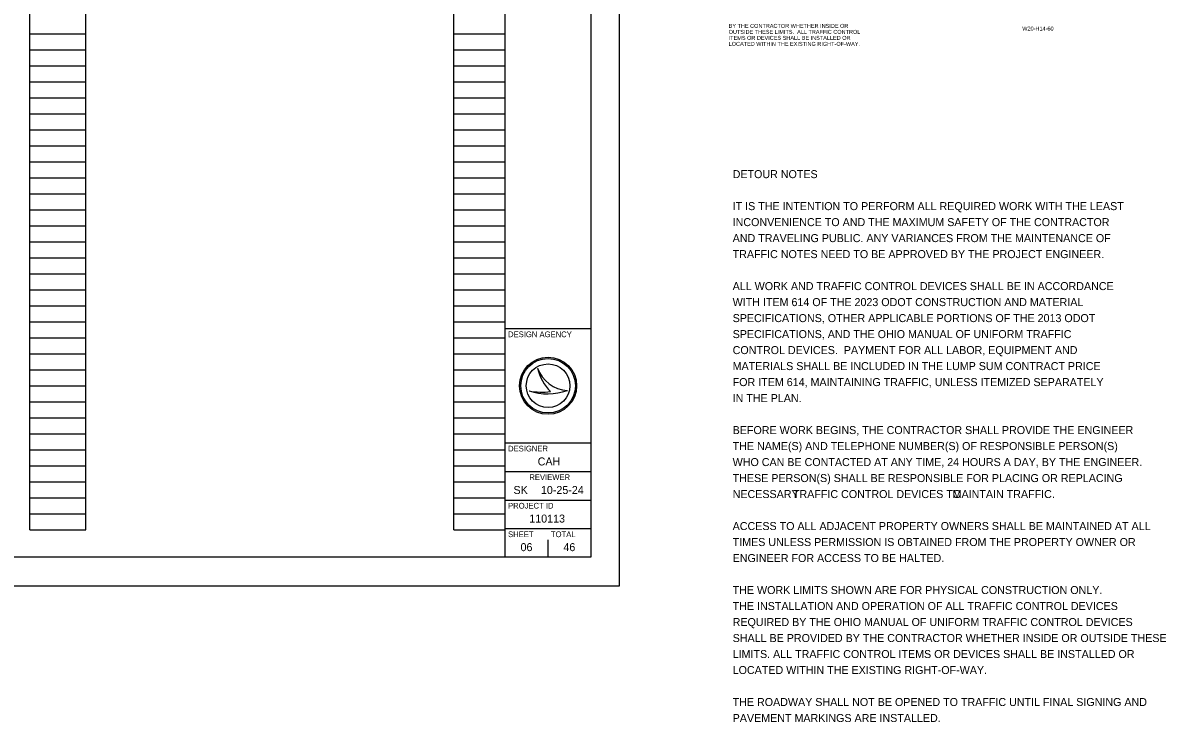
# Model space of a CAD drawing. Extents: x -98 to 46, y -2 to 66.
# Drawn here: x 23.56 to 43.57, y -2.39 to 9.85 of the extents above; entities that cross this region are included whole.
import ezdxf

# ---------------------------------------------------------------- set-up
doc = ezdxf.new("R2010")
doc.units = 0
for name, color, linetype in [('SC_Scratch1', 7, 'Continuous'), ('SH_Border', 7, 'Continuous'), ('SH_Cut_Line', 7, 'Continuous'), ('SH_Data', 7, 'Continuous'), ('SN_P_Text', 7, 'Continuous')]:
    doc.layers.add(name, color=color, linetype=linetype)

msp = doc.modelspace()

# ---------------------------------------------------------------- linework, layer by layer
at = {"layer": 'SH_Border'}
for p, q in [((32, 0.5), (32, 21.5)), ((32, 4.5), (33.5, 4.5)), ((32, 2.5), (33.5, 2.5)), ((32, 2), (33.5, 2)), ((32, 1.5), (33.5, 1.5)), ((32, 1), (33.5, 1))]:
    msp.add_line(p, q, dxfattribs=at)
msp.add_lwpolyline([(1.5, 21.5), (33.5, 21.5), (33.5, 0.5), (1.5, 0.5)], close=True, dxfattribs=at)
at = {"layer": 'SH_Cut_Line'}
msp.add_lwpolyline([(0, 0), (34, 0), (34, 22), (0, 22)], close=True, dxfattribs=at)
at = {"layer": 'SH_Data'}
for p, q in [((23.68, 0.98), (23.68, 21.14)), ((24.66, 0.98), (24.66, 21.14)), ((31.1, 0.98), (31.1, 21.14)), ((32, 0.98), (32, 21.14)), ((23.68, 9.66), (24.66, 9.66)), ((31.1, 9.66), (32, 9.66)), ((23.68, 9.38), (24.66, 9.38)), ((31.1, 9.38), (32, 9.38)), ((23.68, 9.1), (24.66, 9.1)), ((31.1, 9.1), (32, 9.1)), ((23.68, 8.82), (24.66, 8.82)), ((31.1, 8.82), (32, 8.82)), ((23.68, 8.54), (24.66, 8.54)), ((31.1, 8.54), (32, 8.54)), ((23.68, 8.26), (24.66, 8.26)), ((31.1, 8.26), (32, 8.26)), ((23.68, 7.98), (24.66, 7.98)), ((31.1, 7.98), (32, 7.98)), ((23.68, 7.7), (24.66, 7.7)), ((31.1, 7.7), (32, 7.7)), ((23.68, 7.42), (24.66, 7.42)), ((31.1, 7.42), (32, 7.42)), ((23.68, 7.14), (24.66, 7.14)), ((31.1, 7.14), (32, 7.14)), ((23.68, 6.86), (24.66, 6.86)), ((31.1, 6.86), (32, 6.86)), ((23.68, 6.58), (24.66, 6.58)), ((31.1, 6.58), (32, 6.58)), ((23.68, 6.3), (24.66, 6.3)), ((31.1, 6.3), (32, 6.3)), ((23.68, 6.02), (24.66, 6.02)), ((31.1, 6.02), (32, 6.02)), ((23.68, 5.74), (24.66, 5.74)), ((31.1, 5.74), (32, 5.74)), ((23.68, 5.46), (24.66, 5.46)), ((31.1, 5.46), (32, 5.46)), ((23.68, 5.18), (24.66, 5.18)), ((31.1, 5.18), (32, 5.18)), ((23.68, 4.9), (24.66, 4.9)), ((31.1, 4.9), (32, 4.9)), ((23.68, 4.62), (24.66, 4.62)), ((31.1, 4.62), (32, 4.62)), ((23.68, 4.34), (24.66, 4.34)), ((31.1, 4.34), (32, 4.34)), ((23.68, 4.06), (24.66, 4.06)), ((31.1, 4.06), (32, 4.06)), ((32.567, 3.81), (32.567, 3.81)), ((23.68, 3.78), (24.66, 3.78)), ((31.1, 3.78), (32, 3.78)), ((23.68, 3.5), (24.66, 3.5)), ((31.1, 3.5), (32, 3.5)), ((32.417, 3.41), (32.417, 3.41)), ((32.75, 3.5), (32.75, 3.5)), ((33.087, 3.419), (33.087, 3.419)), ((23.68, 3.22), (24.66, 3.22)), ((31.1, 3.22), (32, 3.22)), ((23.68, 2.94), (24.66, 2.94)), ((31.1, 2.94), (32, 2.94)), ((23.68, 2.66), (24.66, 2.66)), ((31.1, 2.66), (32, 2.66)), ((23.68, 2.38), (24.66, 2.38)), ((31.1, 2.38), (32, 2.38)), ((23.68, 2.1), (24.66, 2.1)), ((31.1, 2.1), (32, 2.1)), ((23.68, 1.82), (24.66, 1.82)), ((31.1, 1.82), (32, 1.82)), ((23.68, 1.54), (24.66, 1.54)), ((31.1, 1.54), (32, 1.54)), ((23.68, 1.26), (24.66, 1.26)), ((31.1, 1.26), (32, 1.26)), ((23.68, 0.98), (24.66, 0.98)), ((31.1, 0.98), (32, 0.98)), ((32.375, 0.675), (32.375, 0.675)), ((32.75, 0.5), (32.75, 0.8))]:
    msp.add_line(p, q, dxfattribs=at)
for radius in [0.5, 0.477, 0.477, 0.382]:
    msp.add_circle((32.75, 3.5), radius, dxfattribs=at)
for centre, radius, start, end in [((33.116, 3.998), 0.58, 198.9257, 198.9319), ((33.347, 3.97), 0.796, 191.6379, 191.6421), ((33.116, 3.998), 0.58, 198.9319, 267.1657), ((33.347, 3.97), 0.796, 191.6421, 226.0947), ((32.739, 4.37), 1.013, 251.4576, 290.0832), ((32.648, 4.654), 1.266, 259.4964, 259.4995), ((32.739, 4.37), 1.013, 251.4527, 251.4576), ((32.648, 4.654), 1.266, 259.4995, 276.6672)]:
    msp.add_arc(centre, radius, start, end, dxfattribs=at)

# ---------------------------------------------------------------- texts
at = {"layer": 'SC_Scratch1'}
for s, height, p in [('BY THE CONTRACTOR WHETHER INSIDE OR ', 0.07, (35.91, 9.764)), ('OUTSIDE THESE LIMITS.  ALL TRAFFIC CONTROL ', 0.07, (35.91, 9.659)), ('ITEMS OR DEVICES SHALL BE INSTALLED OR ', 0.07, (35.91, 9.554)), ('LOCATED WITHIN THE EXISTING RIGHT-OF-WAY.', 0.07, (35.91, 9.449)), ('DETOUR NOTES', 0.14, (35.98, 7.134)), ('IT IS THE INTENTION TO PERFORM ALL REQUIRED WORK WITH THE LEAST', 0.14, (35.98, 6.574)), ('INCONVENIENCE TO AND THE MAXIMUM SAFETY OF THE CONTRACTOR ', 0.14, (35.98, 6.294)), ('AND TRAVELING PUBLIC. ANY VARIANCES FROM THE MAINTENANCE OF ', 0.14, (35.98, 6.014)), ('TRAFFIC NOTES NEED TO BE APPROVED BY THE PROJECT ENGINEER.', 0.14, (35.98, 5.734)), ('ALL WORK AND TRAFFIC CONTROL DEVICES SHALL BE IN ACCORDANCE ', 0.14, (35.98, 5.174)), ('WITH ITEM 614 OF THE 2023 ODOT CONSTRUCTION AND MATERIAL ', 0.14, (35.98, 4.894)), ('SPECIFICATIONS, OTHER APPLICABLE PORTIONS OF THE 2013 ODOT ', 0.14, (35.98, 4.614)), ('SPECIFICATIONS, AND THE OHIO MANUAL OF UNIFORM TRAFFIC ', 0.14, (35.98, 4.334)), ('CONTROL DEVICES.  PAYMENT FOR ALL LABOR, EQUIPMENT AND ', 0.14, (35.98, 4.054)), ('MATERIALS SHALL BE INCLUDED IN THE LUMP SUM CONTRACT PRICE ', 0.14, (35.98, 3.774)), ('FOR ITEM 614, MAINTAINING TRAFFIC, UNLESS ITEMIZED SEPARATELY ', 0.14, (35.98, 3.494)), ('IN THE PLAN.', 0.14, (35.98, 3.214)), ('BEFORE WORK BEGINS, THE CONTRACTOR SHALL PROVIDE THE ENGINEER ', 0.14, (35.98, 2.654)), ('THE NAME(S) AND TELEPHONE NUMBER(S) OF RESPONSIBLE PERSON(S) ', 0.14, (35.98, 2.374)), ('WHO CAN BE CONTACTED AT ANY TIME, 24 HOURS A DAY, BY THE ENGINEER.  ', 0.14, (35.98, 2.094)), ('THESE PERSON(S) SHALL BE RESPONSIBLE FOR PLACING OR REPLACING ', 0.14, (35.98, 1.814)), ('NECESSARY ', 0.14, (35.98, 1.534)), ('TRAFFIC CONTROL DEVICES TO ', 0.14, (37.035, 1.534)), ('MAINTAIN TRAFFIC.', 0.14, (39.829, 1.534)), ('ACCESS TO ALL ADJACENT PROPERTY OWNERS SHALL BE MAINTAINED AT ALL ', 0.14, (35.98, 0.974)), ('TIMES UNLESS PERMISSION IS OBTAINED FROM THE PROPERTY OWNER OR', 0.14, (35.98, 0.694)), ('ENGINEER FOR ACCESS TO BE HALTED.', 0.14, (35.98, 0.414)), ('THE WORK LIMITS SHOWN ARE FOR PHYSICAL CONSTRUCTION ONLY.  ', 0.14, (35.98, -0.146)), ('THE INSTALLATION AND OPERATION OF ALL TRAFFIC CONTROL DEVICES ', 0.14, (35.98, -0.426)), ('REQUIRED BY THE OHIO MANUAL OF UNIFORM TRAFFIC CONTROL DEVICES', 0.14, (35.98, -0.706)), ('SHALL BE PROVIDED BY THE CONTRACTOR WHETHER INSIDE OR OUTSIDE THESE ', 0.14, (35.98, -0.986)), ('LIMITS. ALL TRAFFIC CONTROL ITEMS OR DEVICES SHALL BE INSTALLED OR ', 0.14, (35.98, -1.266)), ('LOCATED WITHIN THE EXISTING RIGHT-OF-WAY.', 0.14, (35.98, -1.546)), ('THE ROADWAY SHALL NOT BE OPENED TO TRAFFIC UNTIL FINAL SIGNING AND ', 0.14, (35.98, -2.106)), ('PAVEMENT MARKINGS ARE INSTALLED.', 0.14, (35.98, -2.386))]:
    msp.add_text(s, height=height, dxfattribs=at).set_placement(p)
at = {"layer": 'SH_Data'}
for s, height, p in [('DESIGN AGENCY', 0.1, (32.05, 4.35)), ('DESIGNER', 0.1, (32.05, 2.35)), ('CAH', 0.14, (32.568, 2.105)), ('REVIEWER', 0.1, (32.422, 1.85)), ('SK', 0.14, (32.145, 1.605)), ('10-25-24', 0.14, (32.625, 1.605)), ('PROJECT ID', 0.1, (32.05, 1.35)), ('110113', 0.14, (32.421, 1.105)), ('SHEET', 0.1, (32.05, 0.85)), ('TOTAL', 0.1, (32.8, 0.85)), ('06', 0.14, (32.268, 0.605)), ('46', 0.14, (33.018, 0.605))]:
    msp.add_text(s, height=height, dxfattribs=at).set_placement(p)
at = {"layer": 'SN_P_Text'}
msp.add_text('W20-H14-60', height=0.07, dxfattribs=at).set_placement((41.048, 9.717))

doc.saveas('drawing.dxf')
